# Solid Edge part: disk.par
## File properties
Author: Binay
Template: sync ansi part.par
Last saved by: CADCIM
Revision: 15
Application: Solid Edge
Accuracy: 0.990
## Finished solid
Body 1: solid body, 19 faces, 50 edges, 32 vertices.
  Faces by surface: plane 10, cylinder 9
  Edges by curve: line 32, circle 18
Bounding box of the edges (mm): 50.402 x 50.402 x 3.175, from (2.9188, 47.4242, -1.5875) to (53.3204, 97.8258, 1.5875).
Cylindrical faces by radius (mm): R3.175 x4, R12.7 x1, R25.4 x4
Planar faces by outward normal: +x 2, +y 2, +z 1, -x 2, -y 2, -z 1
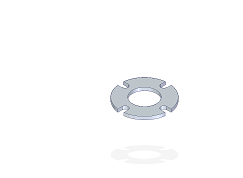
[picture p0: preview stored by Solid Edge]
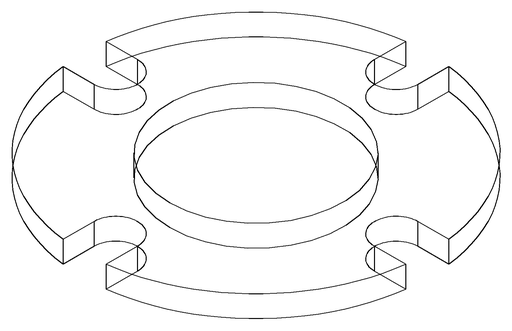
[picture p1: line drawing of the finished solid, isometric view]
